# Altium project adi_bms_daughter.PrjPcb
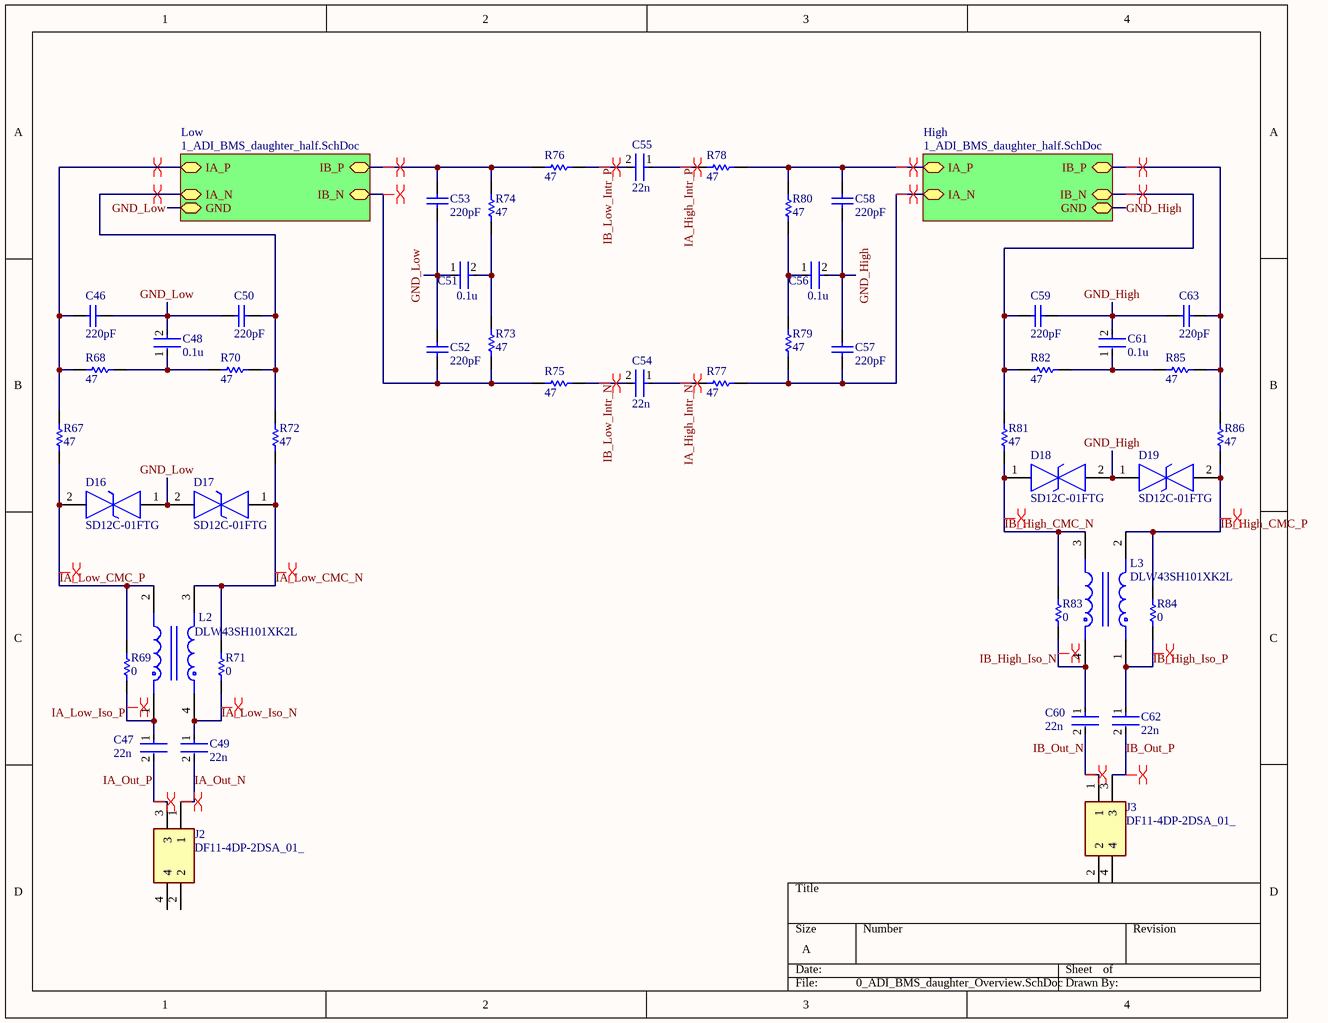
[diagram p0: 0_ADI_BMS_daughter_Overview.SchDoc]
2 sheets, 306 parts. Net scope: hierarchical (ports join the sheet entries above them; power ports are global).
Board file: ADI_BMS_daughter.PcbDoc
Sheets:
  0_ADI_BMS_daughter_Overview.SchDoc
    Low = 1_ADI_BMS_daughter_half.SchDoc
    High = 1_ADI_BMS_daughter_half.SchDoc

## Sheet 0_ADI_BMS_daughter_Overview.SchDoc
size A; SheetNumber: 1; SheetTotal: 2

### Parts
C46  value 220pF  [CAPC0603(1608)100_L]  (hidden comment: CGA3E2C0G2A221J080AA)
C47  22n  [FP-C3225-250-0_4-IPC_B]
C48  0.1u  [CAPC0603(1608)100_L]
C49  22n  [FP-C3225-250-0_4-IPC_B]
C50  value 220pF  [CAPC0603(1608)100_L]  (hidden comment: CGA3E2C0G2A221J080AA)
C51  0.1u  [CAPC0603(1608)100_L]
C52  value 220pF  [CAPC0603(1608)100_L]  (hidden comment: CGA3E2C0G2A221J080AA)
C53  value 220pF  [CAPC0603(1608)100_L]  (hidden comment: CGA3E2C0G2A221J080AA)
C54  22n  [FP-C3225-250-0_4-IPC_B]
C55  22n  [FP-C3225-250-0_4-IPC_B]
C56  0.1u  [CAPC0603(1608)100_L]
C57  value 220pF  [CAPC0603(1608)100_L]  (hidden comment: CGA3E2C0G2A221J080AA)
C58  value 220pF  [CAPC0603(1608)100_L]  (hidden comment: CGA3E2C0G2A221J080AA)
C59  value 220pF  [CAPC0603(1608)100_L]  (hidden comment: CGA3E2C0G2A221J080AA)
C60  22n  [FP-C3225-250-0_4-IPC_B]
C61  0.1u  [CAPC0603(1608)100_L]
C62  22n  [FP-C3225-250-0_4-IPC_B]
C63  value 220pF  [CAPC0603(1608)100_L]  (hidden comment: CGA3E2C0G2A221J080AA)
D16  SD12C-01FTG  [SOD2613X114N]
D17  SD12C-01FTG  [SOD2613X114N]
D18  SD12C-01FTG  [SOD2613X114N]
D19  SD12C-01FTG  [SOD2613X114N]
J2  DF11-4DP-2DSA_01_  [SHDR4W50P200_2X2_600X500X660P]
J3  DF11-4DP-2DSA_01_  [SHDR4W50P200_2X2_600X500X660P]
L2  DLW43SH101XK2L  [FP-DLW43-0_2-t2_6-e0_6-MFG]
L3  DLW43SH101XK2L  [FP-DLW43-0_2-t2_6-e0_6-MFG]
R67  value 47  [RESC0603(1608)_L]  (hidden comment: ESR03EZPJ470)
R68  value 47  [RESC0603(1608)_L]  (hidden comment: ESR03EZPJ470)
R69  value 0  [RESC0603(1608)_L]  (hidden comment: RMCF0603ZT0R00)
R70  value 47  [RESC0603(1608)_L]  (hidden comment: ESR03EZPJ470)
R71  value 0  [RESC0603(1608)_L]  (hidden comment: RMCF0603ZT0R00)
R72  value 47  [RESC0603(1608)_L]  (hidden comment: ESR03EZPJ470)
R73  value 47  [RESC0603(1608)_L]  (hidden comment: ESR03EZPJ470)
R74  value 47  [RESC0603(1608)_L]  (hidden comment: ESR03EZPJ470)
R75  value 47  [RESC0603(1608)_L]  (hidden comment: ESR03EZPJ470)
R76  value 47  [RESC0603(1608)_L]  (hidden comment: ESR03EZPJ470)
R77  value 47  [RESC0603(1608)_L]  (hidden comment: ESR03EZPJ470)
R78  value 47  [RESC0603(1608)_L]  (hidden comment: ESR03EZPJ470)
R79  value 47  [RESC0603(1608)_L]  (hidden comment: ESR03EZPJ470)
R80  value 47  [RESC0603(1608)_L]  (hidden comment: ESR03EZPJ470)
R81  value 47  [RESC0603(1608)_L]  (hidden comment: ESR03EZPJ470)
R82  value 47  [RESC0603(1608)_L]  (hidden comment: ESR03EZPJ470)
R83  value 0  [RESC0603(1608)_L]  (hidden comment: RMCF0603ZT0R00)
R84  value 0  [RESC0603(1608)_L]  (hidden comment: RMCF0603ZT0R00)
R85  value 47  [RESC0603(1608)_L]  (hidden comment: ESR03EZPJ470)
R86  value 47  [RESC0603(1608)_L]  (hidden comment: ESR03EZPJ470)

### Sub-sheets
High = 1_ADI_BMS_daughter_half.SchDoc: IA_P (bidir), IA_N (bidir), IB_P (bidir), IB_N (bidir), GND (bidir)
Low = 1_ADI_BMS_daughter_half.SchDoc: IA_P (bidir), IA_N (bidir), IB_P (bidir), IB_N (bidir), GND (bidir)

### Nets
GND_High: C56.2 C57.2 C58.1 C59.2 C61.2 C63.1 D18.2 D19.1 ; sheet High/GND  [project net GND]
GND_Low: C46.2 C48.2 C50.1 C51.1 C52.2 C53.1 D16.1 D17.2 ; sheet Low/GND  [project net GND]
IA_High_Intr_N: C54.1 R77.2
IA_High_Intr_P: C55.1 R78.2
IA_Low_CMC_N: D17.1 L2.3 R71.2 R72.1
IA_Low_CMC_P: D16.2 L2.2 R67.1 R69.2
IA_Low_Iso_N: C49.1 L2.4 R71.1
IA_Low_Iso_P: C47.1 L2.1 R69.1
IA_N: C50.2 R70.1 R72.2 ; sheet Low/IA_N
IA_N: C57.1 R77.1 R79.1 ; sheet High/IA_N  [a separate net that carries the same name]
IA_Out_N: C49.2 J2.1
IA_Out_P: C47.2 J2.3
IA_P: C46.1 R67.2 R68.2 ; sheet Low/IA_P
IA_P: C58.2 R78.1 R80.1 ; sheet High/IA_P  [a separate net that carries the same name]
IB_High_CMC_N: D18.1 L3.3 R81.1 R83.2
IB_High_CMC_P: D19.2 L3.2 R84.2 R86.1
IB_High_Iso_N: C60.1 L3.4 R83.1
IB_High_Iso_P: C62.1 L3.1 R84.1
IB_Low_Intr_N: C54.2 R75.1
IB_Low_Intr_P: C55.2 R76.1
IB_N: C52.1 R73.1 R75.2 ; sheet Low/IB_N
IB_N: C59.1 R81.2 R82.2 ; sheet High/IB_N  [a separate net that carries the same name]
IB_Out_N: C60.2 J3.1
IB_Out_P: C62.2 J3.3
IB_P: C53.2 R74.2 R76.2 ; sheet Low/IB_P
IB_P: C63.2 R85.1 R86.2 ; sheet High/IB_P  [a separate net that carries the same name]
NetC48_1: C48.1 R68.1 R70.2
NetC51_2: C51.2 R73.2 R74.1
NetC56_1: C56.1 R79.2 R80.2
NetC61_1: C61.1 R82.1 R85.2

Not connected (* = marked no-connect by the designer): J2 2 4; J3 2 4

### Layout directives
differential pair: IA_High_Intr_N, IA_High_Intr_P, IA_Low_CMC_N, IA_Low_CMC_P, IA_Low_Iso_N, IA_Low_Iso_P, IA_N, IA_Out_N, IA_Out_P, IA_P, IB_High_CMC_N, IB_High_CMC_P, IB_High_Iso_N, IB_High_Iso_P, IB_Low_Intr_N, IB_Low_Intr_P, IB_N, IB_Out_N, IB_Out_P, IB_P

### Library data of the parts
C46 C50 C52 C53 C57-C59 C63 = CMP-001-00103-1: Ceramic Capacitor, Multilayer, Ceramic, 100V, 5% +Tol, 5% -Tol, C0G, -/+30ppm/Cel TC, 0.00022uF, Surface Mount, 0603
C47 C49 C54 C55 C60 C62 = CMP-08246-005724-1: Multilayer Ceramic Capacitors 22nF ±5% 1000V C0G SMD 1210; Voltage Rating: 1kV
C48 C51 C56 C61 = CMP-002-00083-1: Ceramic Capacitor, Multilayer, Ceramic, 100V, 10% +Tol, 10% -Tol, X7R, 15% TC, 0.1uF, Surface Mount, 0603 GCJ188R72A104KA01D
D16-D19 = SD12C-01FTG: TVS Diode (Bi-directional); Manufacturer_Name: LITTELFUSE
J2 J3 = DF11-4DP-2DSA_01_: Connector; Manufacturer_Name: Hirose; Manufacturer_Part_Number: DF11-4DP-2DSA(01)
L2 L3 = CMP-06045-000059-1: CMC 100UH 200MA 2LN SMD AEC-Q200; Shielding: Unshielded; Tolerance: 50%; DC Resistance (DCR): 2R; Voltage Rating: 50V; Test Frequency: 1MHz; Number of Lines: 2
R67 R68 R70 R72-R82 R85 R86 = CMP-009-00206-1: Fixed Resistor, Metal Glaze/thick Film, 0.25W, 47ohm, 150V, 5% +/-Tol, 200ppm/Cel, Surface Mount, 0603; Power: 250mW
R69 R71 R83 R84 = CMP-009-00243-1: Fixed Resistor, Metal Glaze/thick Film, 0.1W, 0ohm, Surface Mount, 0603; Power: 100mW

## Sheet 1_ADI_BMS_daughter_half.SchDoc
size 431 x 279 mm; SheetNumber: 2; SheetTotal: 2
Used 2 times, as channels Low, High. Parts and nets are listed once, with the designators drawn on the sheet.
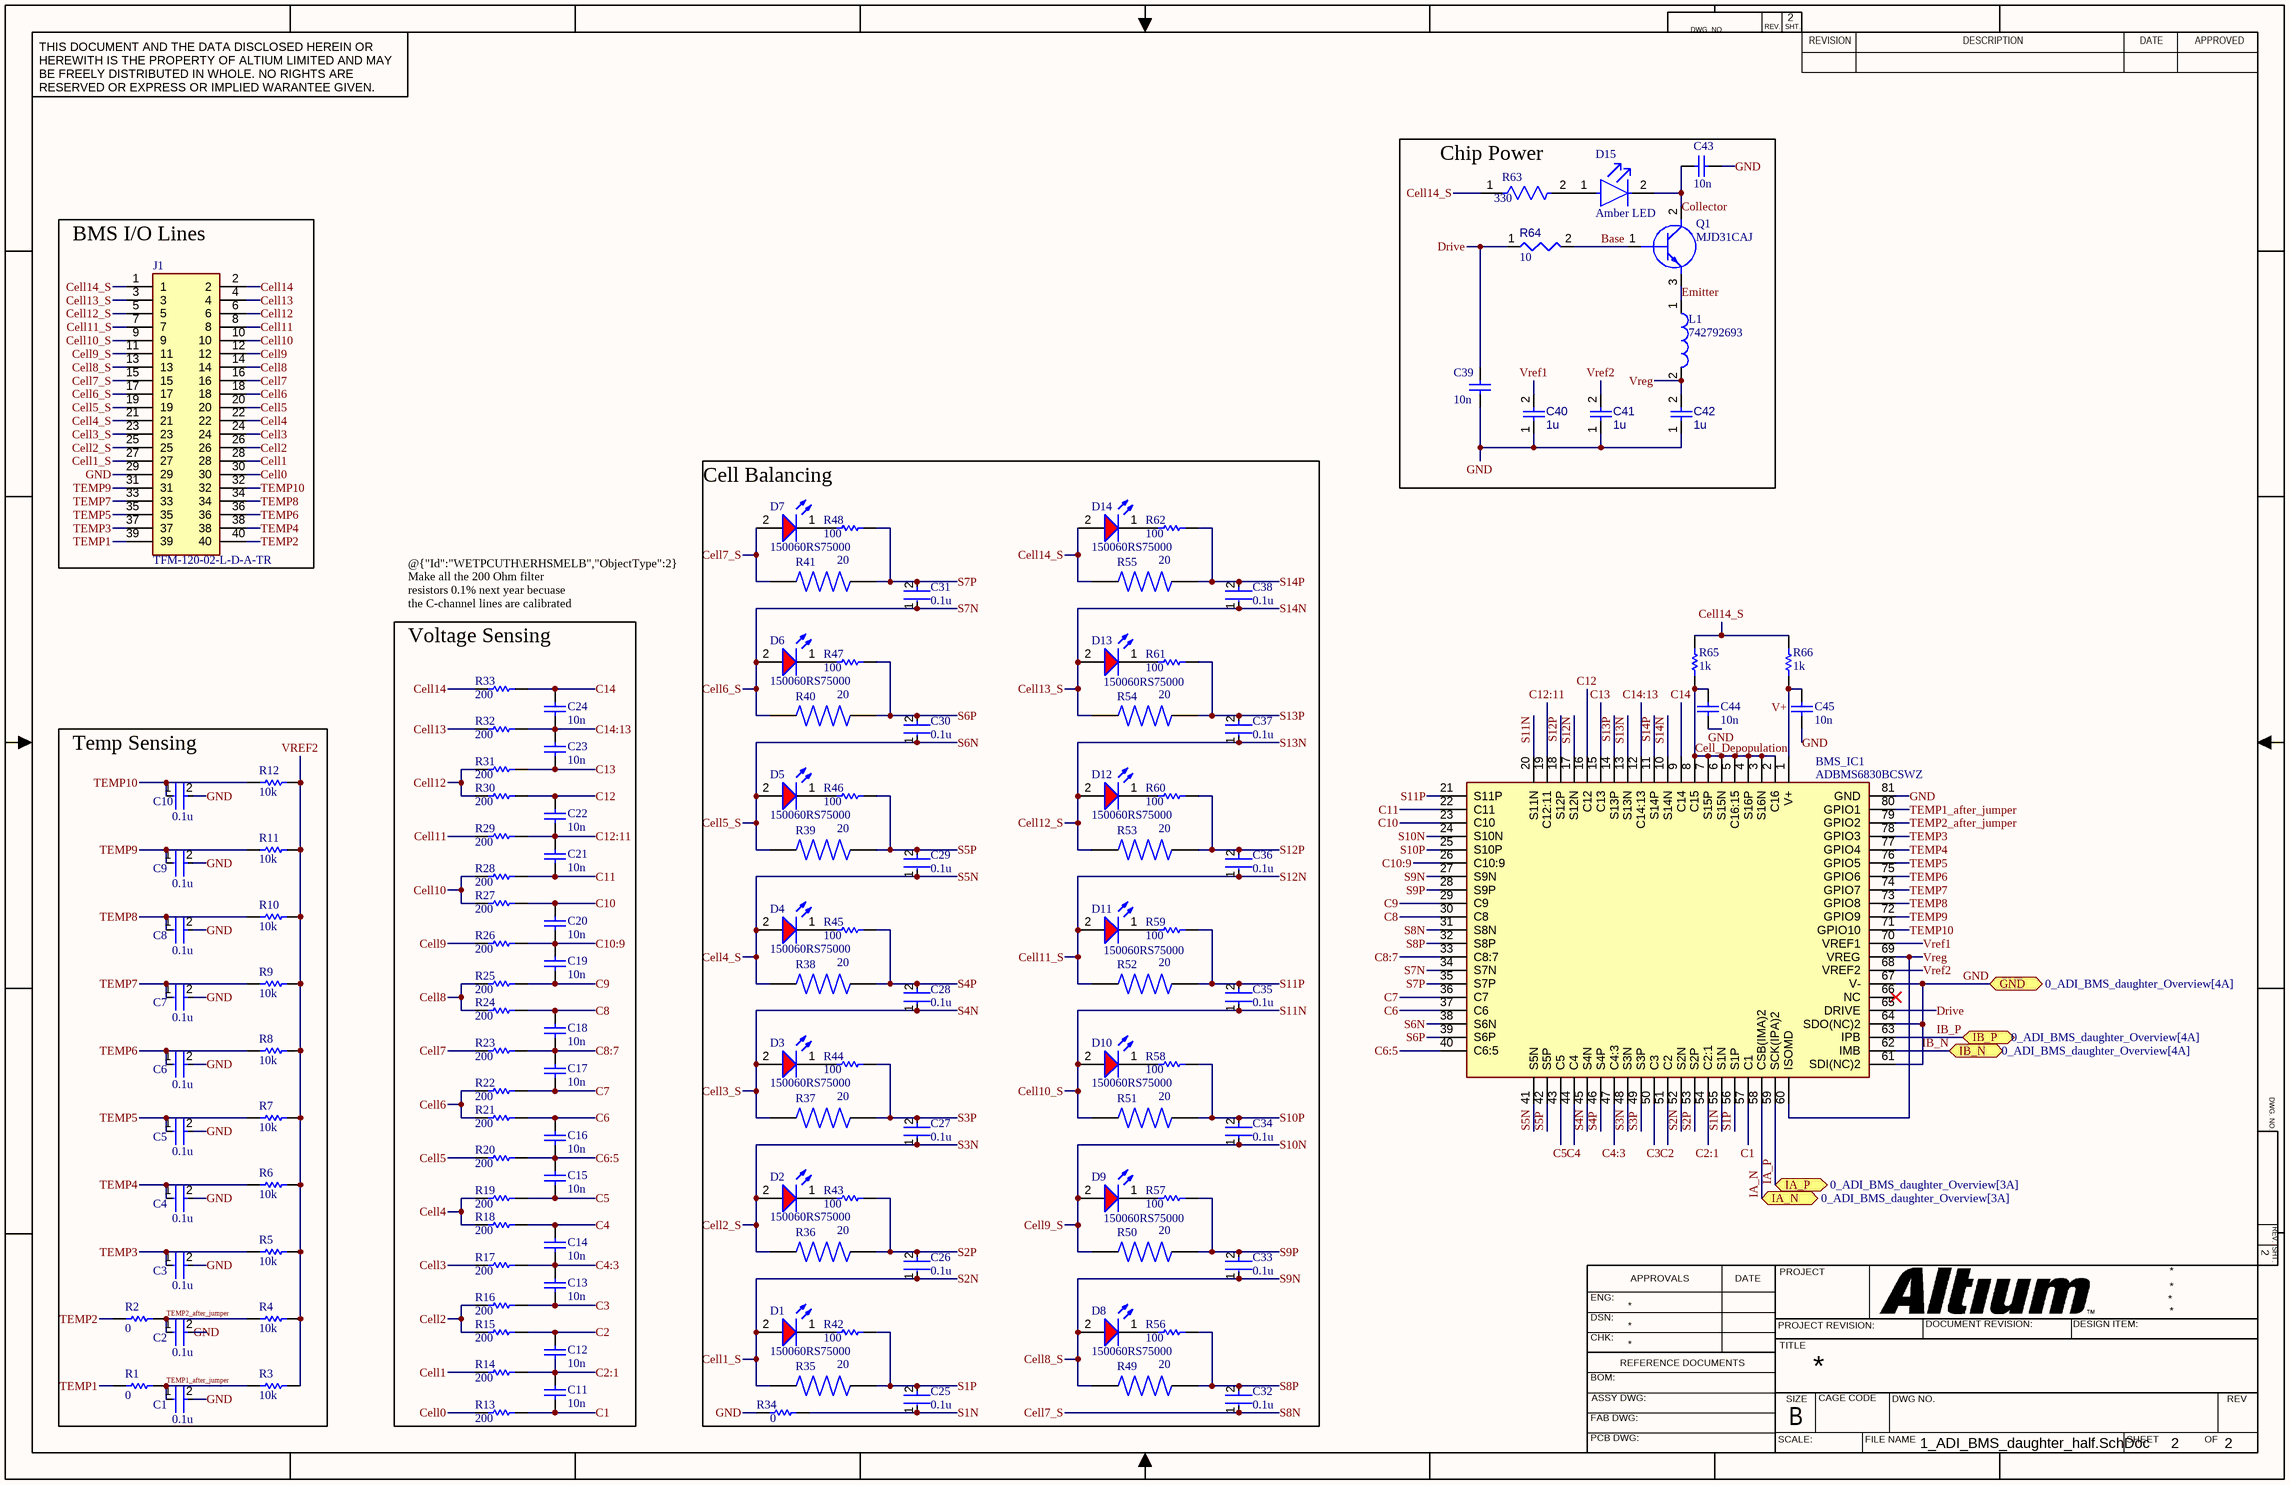
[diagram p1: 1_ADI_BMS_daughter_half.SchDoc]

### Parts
BMS_IC1  ADBMS6830BCSWZ  [QFP50P1400X1400X160-81N]
C1  0.1u  [CAPC0603(1608)100_L]
C2  0.1u  [CAPC0603(1608)100_L]
C3  0.1u  [CAPC0603(1608)100_L]
C4  0.1u  [CAPC0603(1608)100_L]
C5  0.1u  [CAPC0603(1608)100_L]
C6  0.1u  [CAPC0603(1608)100_L]
C7  0.1u  [CAPC0603(1608)100_L]
C8  0.1u  [CAPC0603(1608)100_L]
C9  0.1u  [CAPC0603(1608)100_L]
C10  0.1u  [CAPC0603(1608)100_L]
C11  value 10n  [CAPC0603(1608)100_L]  (hidden comment: C1608X7R2A103K080AA)
C12  value 10n  [CAPC0603(1608)100_L]  (hidden comment: C1608X7R2A103K080AA)
C13  value 10n  [CAPC0603(1608)100_L]  (hidden comment: C1608X7R2A103K080AA)
C14  value 10n  [CAPC0603(1608)100_L]  (hidden comment: C1608X7R2A103K080AA)
C15  value 10n  [CAPC0603(1608)100_L]  (hidden comment: C1608X7R2A103K080AA)
C16  value 10n  [CAPC0603(1608)100_L]  (hidden comment: C1608X7R2A103K080AA)
C17  value 10n  [CAPC0603(1608)100_L]  (hidden comment: C1608X7R2A103K080AA)
C18  value 10n  [CAPC0603(1608)100_L]  (hidden comment: C1608X7R2A103K080AA)
C19  value 10n  [CAPC0603(1608)100_L]  (hidden comment: C1608X7R2A103K080AA)
C20  value 10n  [CAPC0603(1608)100_L]  (hidden comment: C1608X7R2A103K080AA)
C21  value 10n  [CAPC0603(1608)100_L]  (hidden comment: C1608X7R2A103K080AA)
C22  value 10n  [CAPC0603(1608)100_L]  (hidden comment: C1608X7R2A103K080AA)
C23  value 10n  [CAPC0603(1608)100_L]  (hidden comment: C1608X7R2A103K080AA)
C24  value 10n  [CAPC0603(1608)100_L]  (hidden comment: C1608X7R2A103K080AA)
C25  0.1u  [CAPC0603(1608)100_L]
C26  0.1u  [CAPC0603(1608)100_L]
C27  0.1u  [CAPC0603(1608)100_L]
C28  0.1u  [CAPC0603(1608)100_L]
C29  0.1u  [CAPC0603(1608)100_L]
C30  0.1u  [CAPC0603(1608)100_L]
C31  0.1u  [CAPC0603(1608)100_L]
C32  0.1u  [CAPC0603(1608)100_L]
C33  0.1u  [CAPC0603(1608)100_L]
C34  0.1u  [CAPC0603(1608)100_L]
C35  0.1u  [CAPC0603(1608)100_L]
C36  0.1u  [CAPC0603(1608)100_L]
C37  0.1u  [CAPC0603(1608)100_L]
C38  0.1u  [CAPC0603(1608)100_L]
C39  value 10n  [CAPC0603(1608)100_L]  (hidden comment: C1608X7R2A103K080AA)
C40  1u  [CAPC0805(2012)145_L]
C41  1u  [CAPC0805(2012)145_L]
C42  1u  [CAPC0805(2012)145_L]
C43  value 10n  [CAPC0603(1608)100_L]  (hidden comment: C1608X7R2A103K080AA)
C44  value 10n  [CAPC0603(1608)100_L]  (hidden comment: C1608X7R2A103K080AA)
C45  value 10n  [CAPC0603(1608)100_L]  (hidden comment: C1608X7R2A103K080AA)
D1  150060RS75000  [WL-SMCW_0603_150060xx75000]
D2  150060RS75000  [WL-SMCW_0603_150060xx75000]
D3  150060RS75000  [WL-SMCW_0603_150060xx75000]
D4  150060RS75000  [WL-SMCW_0603_150060xx75000]
D5  150060RS75000  [WL-SMCW_0603_150060xx75000]
D6  150060RS75000  [WL-SMCW_0603_150060xx75000]
D7  150060RS75000  [WL-SMCW_0603_150060xx75000]
D8  150060RS75000  [WL-SMCW_0603_150060xx75000]
D9  150060RS75000  [WL-SMCW_0603_150060xx75000]
D10  150060RS75000  [WL-SMCW_0603_150060xx75000]
D11  150060RS75000  [WL-SMCW_0603_150060xx75000]
D12  150060RS75000  [WL-SMCW_0603_150060xx75000]
D13  150060RS75000  [WL-SMCW_0603_150060xx75000]
D14  150060RS75000  [WL-SMCW_0603_150060xx75000]
D15  Amber LED  [FP-CLM3C-AKW-MFG]
J1  TFM-120-02-L-D-A-TR  [TFM12002LDATR]
L1  742792693  [SMD-0603]
Q1  MJD31CAJ  [MJD31CAJ]
R1  value 0  [RESC0603(1608)_L]  (hidden comment: RMCF0603ZT0R00)
R2  value 0  [RESC0603(1608)_L]  (hidden comment: RMCF0603ZT0R00)
R3  value 10k  [RESC0603(1608)_L]  (hidden comment: RT0603BRD0710KL)
R4  value 10k  [RESC0603(1608)_L]  (hidden comment: RT0603BRD0710KL)
R5  value 10k  [RESC0603(1608)_L]  (hidden comment: RT0603BRD0710KL)
R6  value 10k  [RESC0603(1608)_L]  (hidden comment: RT0603BRD0710KL)
R7  value 10k  [RESC0603(1608)_L]  (hidden comment: RT0603BRD0710KL)
R8  value 10k  [RESC0603(1608)_L]  (hidden comment: RT0603BRD0710KL)
R9  value 10k  [RESC0603(1608)_L]  (hidden comment: RT0603BRD0710KL)
R10  value 10k  [RESC0603(1608)_L]  (hidden comment: RT0603BRD0710KL)
R11  value 10k  [RESC0603(1608)_L]  (hidden comment: RT0603BRD0710KL)
R12  value 10k  [RESC0603(1608)_L]  (hidden comment: RT0603BRD0710KL)
R13  value 200  [RESC0603(1608)_L]  (hidden comment: ESR03EZPF2000)
R14  value 200  [RESC0603(1608)_L]  (hidden comment: ESR03EZPF2000)
R15  value 200  [RESC0603(1608)_L]  (hidden comment: ESR03EZPF2000)
R16  value 200  [RESC0603(1608)_L]  (hidden comment: ESR03EZPF2000)
R17  value 200  [RESC0603(1608)_L]  (hidden comment: ESR03EZPF2000)
R18  value 200  [RESC0603(1608)_L]  (hidden comment: ESR03EZPF2000)
R19  value 200  [RESC0603(1608)_L]  (hidden comment: ESR03EZPF2000)
R20  value 200  [RESC0603(1608)_L]  (hidden comment: ESR03EZPF2000)
R21  value 200  [RESC0603(1608)_L]  (hidden comment: ESR03EZPF2000)
R22  value 200  [RESC0603(1608)_L]  (hidden comment: ESR03EZPF2000)
R23  value 200  [RESC0603(1608)_L]  (hidden comment: ESR03EZPF2000)
R24  value 200  [RESC0603(1608)_L]  (hidden comment: ESR03EZPF2000)
R25  value 200  [RESC0603(1608)_L]  (hidden comment: ESR03EZPF2000)
R26  value 200  [RESC0603(1608)_L]  (hidden comment: ESR03EZPF2000)
R27  value 200  [RESC0603(1608)_L]  (hidden comment: ESR03EZPF2000)
R28  value 200  [RESC0603(1608)_L]  (hidden comment: ESR03EZPF2000)
R29  value 200  [RESC0603(1608)_L]  (hidden comment: ESR03EZPF2000)
R30  value 200  [RESC0603(1608)_L]  (hidden comment: ESR03EZPF2000)
R31  value 200  [RESC0603(1608)_L]  (hidden comment: ESR03EZPF2000)
R32  value 200  [RESC0603(1608)_L]  (hidden comment: ESR03EZPF2000)
R33  value 200  [RESC0603(1608)_L]  (hidden comment: ESR03EZPF2000)
R34  value 0  [RESC0603(1608)_L]  (hidden comment: RMCF0603ZT0R00)
R35  value 20  [RESC5025X70N]  (hidden comment: RMCP2010FT20R0)
R36  value 20  [RESC5025X70N]  (hidden comment: RMCP2010FT20R0)
R37  value 20  [RESC5025X70N]  (hidden comment: RMCP2010FT20R0)
R38  value 20  [RESC5025X70N]  (hidden comment: RMCP2010FT20R0)
R39  value 20  [RESC5025X70N]  (hidden comment: RMCP2010FT20R0)
R40  value 20  [RESC5025X70N]  (hidden comment: RMCP2010FT20R0)
R41  value 20  [RESC5025X70N]  (hidden comment: RMCP2010FT20R0)
R42  100  [RESC0603(1608)_L]
R43  100  [RESC0603(1608)_L]
R44  100  [RESC0603(1608)_L]
R45  100  [RESC0603(1608)_L]
R46  100  [RESC0603(1608)_L]
R47  100  [RESC0603(1608)_L]
R48  100  [RESC0603(1608)_L]
R49  value 20  [RESC5025X70N]  (hidden comment: RMCP2010FT20R0)
R50  value 20  [RESC5025X70N]  (hidden comment: RMCP2010FT20R0)
R51  value 20  [RESC5025X70N]  (hidden comment: RMCP2010FT20R0)
R52  value 20  [RESC5025X70N]  (hidden comment: RMCP2010FT20R0)
R53  value 20  [RESC5025X70N]  (hidden comment: RMCP2010FT20R0)
R54  value 20  [RESC5025X70N]  (hidden comment: RMCP2010FT20R0)
R55  value 20  [RESC5025X70N]  (hidden comment: RMCP2010FT20R0)
R56  100  [RESC0603(1608)_L]
R57  100  [RESC0603(1608)_L]
R58  100  [RESC0603(1608)_L]
R59  100  [RESC0603(1608)_L]
R60  100  [RESC0603(1608)_L]
R61  100  [RESC0603(1608)_L]
R62  100  [RESC0603(1608)_L]
R63  Resistance: 330  [FP-ESR18-IPC_A]  (hidden comment: ESR18EZPJ331)
R64  value 10  [RESC0603(1608)_L]  (hidden comment: RMCF0603FT10R0)
R65  value 1k  [RESC0603(1608)_L]  (hidden comment: ESR03EZPJ102)
R66  value 1k  [RESC0603(1608)_L]  (hidden comment: ESR03EZPJ102)

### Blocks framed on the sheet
Chip Power: C39-C43 D15 L1 Q1 R63 R64
BMS I/O Lines: J1
Cell Balancing: C25-C38 D1-D14 R34-R62
Voltage Sensing: C11-C24 R13-R33
Temp Sensing: C1-C10 R1-R12

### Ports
GND (bidir, see 0_ADI_BMS_daughter_Overview[4A]), IA_N (bidir, see 0_ADI_BMS_daughter_Overview[3A]), IA_P (bidir, see 0_ADI_BMS_daughter_Overview[3A]), IB_N (bidir, see 0_ADI_BMS_daughter_Overview[4A]), IB_P (bidir, see 0_ADI_BMS_daughter_Overview[4A])

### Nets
Base: Q1.1(B) R64.2
C1: BMS_IC1.57(C1) C11.1 R13.2
C2: BMS_IC1.51(C2) C12.2 R15.2
C2:1: BMS_IC1.54(C2:1) C11.2 C12.1 R14.2
C3: BMS_IC1.50(C3) C13.1 R16.2
C4: BMS_IC1.44(C4) C14.2 R18.2
C4:3: BMS_IC1.47(C4:3) C13.2 C14.1 R17.2
C5: BMS_IC1.43(C5) C15.1 R19.2
C6: BMS_IC1.37(C6) C16.2 R21.2
C6:5: BMS_IC1.40(C6:5) C15.2 C16.1 R20.2
C7: BMS_IC1.36(C7) C17.1 R22.2
C8: BMS_IC1.30(C8) C18.2 R24.2
C8:7: BMS_IC1.33(C8:7) C17.2 C18.1 R23.2
C9: BMS_IC1.29(C9) C19.1 R25.2
C10: BMS_IC1.23(C10) C20.2 R27.2
C10:9: BMS_IC1.26(C10:9) C19.2 C20.1 R26.2
C11: BMS_IC1.22(C11) C21.1 R28.2
C12: BMS_IC1.16(C12) C22.2 R30.2
C12:11: BMS_IC1.19(C12:11) C21.2 C22.1 R29.2
C13: BMS_IC1.15(C13) C23.1 R31.2
C14: BMS_IC1.9(C14) C24.2 R33.2
C14:13: BMS_IC1.12(C14:13) C23.2 C24.1 R32.2
Cell0: J1.30 R13.1
Cell1: J1.28 R14.1
Cell1_S: BMS_IC1.52(S2N) C26.1 D1.2(A) J1.27 R35.1  [also labelled S2N]
Cell2: J1.26 R15.1 R16.1
Cell2_S: BMS_IC1.48(S3N) C27.1 D2.2(A) J1.25 R36.1  [also labelled S3N]
Cell3: J1.24 R17.1
Cell3_S: BMS_IC1.45(S4N) C28.1 D3.2(A) J1.23 R37.1  [also labelled S4N]
Cell4: J1.22 R18.1 R19.1
Cell4_S: BMS_IC1.41(S5N) C29.1 D4.2(A) J1.21 R38.1  [also labelled S5N]
Cell5: J1.20 R20.1
Cell5_S: BMS_IC1.38(S6N) C30.1 D5.2(A) J1.19 R39.1  [also labelled S6N]
Cell6: J1.18 R21.1 R22.1
Cell6_S: BMS_IC1.34(S7N) C31.1 D6.2(A) J1.17 R40.1  [also labelled S7N]
Cell7: J1.16 R23.1
Cell7_S: BMS_IC1.31(S8N) C32.1 D7.2(A) J1.15 R41.1  [also labelled S8N]
Cell8: J1.14 R24.1 R25.1
Cell8_S: BMS_IC1.27(S9N) C33.1 D8.2(A) J1.13 R49.1  [also labelled S9N]
Cell9: J1.12 R26.1
Cell9_S: BMS_IC1.24(S10N) C34.1 D9.2(A) J1.11 R50.1  [also labelled S10N]
Cell10: J1.10 R27.1 R28.1
Cell10_S: BMS_IC1.20(S11N) C35.1 D10.2(A) J1.9 R51.1  [also labelled S11N]
Cell11: J1.8 R29.1
Cell11_S: BMS_IC1.17(S12N) C36.1 D11.2(A) J1.7 R52.1  [also labelled S12N]
Cell12: J1.6 R30.1 R31.1
Cell12_S: BMS_IC1.13(S13N) C37.1 D12.2(A) J1.5 R53.1  [also labelled S13N]
Cell13: J1.4 R32.1
Cell13_S: BMS_IC1.10(S14N) C38.1 D13.2(A) J1.3 R54.1  [also labelled S14N]
Cell14: J1.2 R33.1
Cell14_S: D14.2(A) J1.1 R55.1 R63.1 R65.1 R66.1
Cell_Depopulation: BMS_IC1.2(C16) BMS_IC1.3(S16N) BMS_IC1.4(S16P) BMS_IC1.5(C16:15) BMS_IC1.6(S15N) BMS_IC1.7(S15P) BMS_IC1.8(C15) C44.2 R65.2
Collector: C43.1 D15.2(C) Q1.2(C)
Drive: BMS_IC1.65(DRIVE) C39.2 R64.1
Emitter: L1.1 Q1.3(E)
GND: BMS_IC1.61(SDI(NC)2) BMS_IC1.64(SDO(NC)2) BMS_IC1.67(V-) BMS_IC1.81(GND) C1.2 C2.2 C3.2 C4.2 C5.2 C6.2 C7.2 C8.2 C9.2 C10.2 C39.1 C40.1 C41.1 C42.1 C43.2 C44.1 C45.2 J1.29 R34.2 ; port GND
IA_N: BMS_IC1.58(CSB(IMA)2) ; port IA_N
IA_P: BMS_IC1.59(SCK(IPA)2) ; port IA_P
IB_N: BMS_IC1.62(IMB) ; port IB_N
IB_P: BMS_IC1.63(IPB) ; port IB_P
S1N: BMS_IC1.55(S1N) C25.1 R34.1
S1P: BMS_IC1.56(S1P) C25.2 R35.2 R42.2
S2P: BMS_IC1.53(S2P) C26.2 R36.2 R43.2
S3P: BMS_IC1.49(S3P) C27.2 R37.2 R44.2
S4P: BMS_IC1.46(S4P) C28.2 R38.2 R45.2
S5P: BMS_IC1.42(S5P) C29.2 R39.2 R46.2
S6P: BMS_IC1.39(S6P) C30.2 R40.2 R47.2
S7P: BMS_IC1.35(S7P) C31.2 R41.2 R48.2
S8P: BMS_IC1.32(S8P) C32.2 R49.2 R56.2
S9P: BMS_IC1.28(S9P) C33.2 R50.2 R57.2
S10P: BMS_IC1.25(S10P) C34.2 R51.2 R58.2
S11P: BMS_IC1.21(S11P) C35.2 R52.2 R59.2
S12P: BMS_IC1.18(S12P) C36.2 R53.2 R60.2
S13P: BMS_IC1.14(S13P) C37.2 R54.2 R61.2
S14P: BMS_IC1.11(S14P) C38.2 R55.2 R62.2
TEMP1: J1.39 R1.2
TEMP1_after_jumper: BMS_IC1.80(GPIO1) C1.1 R1.1 R3.1
TEMP2: J1.40 R2.2
TEMP2_after_jumper: BMS_IC1.79(GPIO2) C2.1 R2.1 R4.1
TEMP3: BMS_IC1.78(GPIO3) C3.1 J1.37 R5.1
TEMP4: BMS_IC1.77(GPIO4) C4.1 J1.38 R6.1
TEMP5: BMS_IC1.76(GPIO5) C5.1 J1.35 R7.1
TEMP6: BMS_IC1.75(GPIO6) C6.1 J1.36 R8.1
TEMP7: BMS_IC1.74(GPIO7) C7.1 J1.33 R9.1
TEMP8: BMS_IC1.73(GPIO8) C8.1 J1.34 R10.1
TEMP9: BMS_IC1.72(GPIO9) C9.1 J1.31 R11.1
TEMP10: BMS_IC1.71(GPIO10) C10.1 J1.32 R12.1
V+: BMS_IC1.1(V+) C45.1 R66.2
Vref1: BMS_IC1.70(VREF1) C40.2
Vref2: BMS_IC1.68(VREF2) C41.2 R3.2 R4.2 R5.2 R6.2 R7.2 R8.2 R9.2 R10.2 R11.2 R12.2
Vreg: BMS_IC1.60(ISOMD) BMS_IC1.69(VREG) C42.2 L1.2
NetD1_1: D1.1(K) R42.1
NetD2_1: D2.1(K) R43.1
NetD3_1: D3.1(K) R44.1
NetD4_1: D4.1(K) R45.1
NetD5_1: D5.1(K) R46.1
NetD6_1: D6.1(K) R47.1
NetD7_1: D7.1(K) R48.1
NetD8_1: D8.1(K) R56.1
NetD9_1: D9.1(K) R57.1
NetD10_1: D10.1(K) R58.1
NetD11_1: D11.1(K) R59.1
NetD12_1: D12.1(K) R60.1
NetD13_1: D13.1(K) R61.1
NetD14_1: D14.1(K) R62.1
NetD15_1: D15.1(A) R63.2

Not connected (* = marked no-connect by the designer): BMS_IC1 66(NC)*

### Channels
Low: designators BMS_IC1=BMS_IC1_Low C1=C1_Low C2=C2_Low C3=C3_Low C4=C4_Low C5=C5_Low C6=C6_Low C7=C7_Low C8=C8_Low C9=C9_Low C10=C10_Low C11=C11_Low C12=C12_Low C13=C13_Low C14=C14_Low C15=C15_Low C16=C16_Low C17=C17_Low C18=C18_Low C19=C19_Low C20=C20_Low C21=C21_Low C22=C22_Low C23=C23_Low C24=C24_Low C25=C25_Low C26=C26_Low C27=C27_Low C28=C28_Low C29=C29_Low C30=C30_Low C31=C31_Low C32=C32_Low C33=C33_Low C34=C34_Low C35=C35_Low C36=C36_Low C37=C37_Low C38=C38_Low C39=C39_Low C40=C40_Low C41=C41_Low C42=C42_Low C43=C43_Low C44=C44_Low C45=C45_Low D1=D1_Low D2=D2_Low D3=D3_Low D4=D4_Low D5=D5_Low D6=D6_Low D7=D7_Low D8=D8_Low D9=D9_Low D10=D10_Low D11=D11_Low D12=D12_Low D13=D13_Low D14=D14_Low D15=D15_Low J1=J1_Low L1=L1_Low Q1=Q1_Low R1=R1_Low R2=R2_Low R3=R3_Low R4=R4_Low R5=R5_Low R6=R6_Low R7=R7_Low R8=R8_Low R9=R9_Low R10=R10_Low R11=R11_Low R12=R12_Low R13=R13_Low R14=R14_Low R15=R15_Low R16=R16_Low R17=R17_Low R18=R18_Low R19=R19_Low R20=R20_Low R21=R21_Low R22=R22_Low R23=R23_Low R24=R24_Low R25=R25_Low R26=R26_Low R27=R27_Low R28=R28_Low R29=R29_Low R30=R30_Low R31=R31_Low R32=R32_Low R33=R33_Low R34=R34_Low R35=R35_Low R36=R36_Low R37=R37_Low R38=R38_Low R39=R39_Low R40=R40_Low R41=R41_Low R42=R42_Low R43=R43_Low R44=R44_Low R45=R45_Low R46=R46_Low R47=R47_Low R48=R48_Low R49=R49_Low R50=R50_Low R51=R51_Low R52=R52_Low R53=R53_Low R54=R54_Low R55=R55_Low R56=R56_Low R57=R57_Low R58=R58_Low R59=R59_Low R60=R60_Low R61=R61_Low R62=R62_Low R63=R63_Low R64=R64#1 R65=R65_Low R66=R66_Low; ports GND=GND IA_N=IA_N IA_P=IA_P IB_N=IB_N IB_P=IB_P
High: designators BMS_IC1=BMS_IC1_High C1=C1_High C2=C2_High C3=C3_High C4=C4_High C5=C5_High C6=C6_High C7=C7_High C8=C8_High C9=C9_High C10=C10_High C11=C11_High C12=C12_High C13=C13_High C14=C14_High C15=C15_High C16=C16_High C17=C17_High C18=C18_High C19=C19_High C20=C20_High C21=C21_High C22=C22_High C23=C23_High C24=C24_High C25=C25_High C26=C26_High C27=C27_High C28=C28_High C29=C29_High C30=C30_High C31=C31_High C32=C32_High C33=C33_High C34=C34_High C35=C35_High C36=C36_High C37=C37_High C38=C38_High C39=C39_High C40=C40_High C41=C41_High C42=C42_High C43=C43_High C44=C44_High C45=C45_High D1=D1_High D2=D2_High D3=D3_High D4=D4_High D5=D5_High D6=D6_High D7=D7_High D8=D8_High D9=D9_High D10=D10_High D11=D11_High D12=D12_High D13=D13_High D14=D14_High D15=D15_High J1=J1_High L1=L1_High Q1=Q1_High R1=R1_High R2=R2_High R3=R3_High R4=R4_High R5=R5_High R6=R6_High R7=R7_High R8=R8_High R9=R9_High R10=R10_High R11=R11_High R12=R12_High R13=R13_High R14=R14_High R15=R15_High R16=R16_High R17=R17_High R18=R18_High R19=R19_High R20=R20_High R21=R21_High R22=R22_High R23=R23_High R24=R24_High R25=R25_High R26=R26_High R27=R27_High R28=R28_High R29=R29_High R30=R30_High R31=R31_High R32=R32_High R33=R33_High R34=R34_High R35=R35_High R36=R36_High R37=R37_High R38=R38_High R39=R39_High R40=R40_High R41=R41_High R42=R42_High R43=R43_High R44=R44_High R45=R45_High R46=R46_High R47=R47_High R48=R48_High R49=R49_High R50=R50_High R51=R51_High R52=R52_High R53=R53_High R54=R54_High R55=R55_High R56=R56_High R57=R57_High R58=R58_High R59=R59_High R60=R60_High R61=R61_High R62=R62_High R63=R63_High R64=R64#2 R65=R65_High R66=R66_High; ports GND=GND IA_N=IA_N IA_P=IA_P IB_N=IB_N IB_P=IB_P

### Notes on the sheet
- @{"Id":"WETPCUTH\ERHSMELB","ObjectType":2} Make all the 200 Ohm filter resistors 0.1% next year becuase the C-channel lines are calibrated for 200 Ohms

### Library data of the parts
BMS_IC1 = ADBMS6830BCSWZ: Integrated Circuit; Manufacturer_Name: Analog Devices
C1-C10 C25-C38 = CMP-002-00083-1: as C48 on sheet 0_ADI_BMS_daughter_Overview
C11-C24 C39 C43-C45 = CMP-009-00202-1: Ceramic Capacitor, Multilayer, Ceramic, 100V, 10% +Tol, 10% -Tol, X7R, 15% TC, 0.01uF, Surface Mount, 0603
C40-C42 = CMP-001-00123-1: Ceramic Capacitor, Multilayer, Ceramic, 100V, 10% +Tol, 10% -Tol, X7S, 22% TC, 1uF, Surface Mount, 0805 / HMK212BC7105KGHTE
D1-D14 = CMP-1426-00001-3: NexarPartId: 29717776; Color: Red; Power Dissipation: 72mW; Max Reverse Voltage (DC): 5V; Peak Wavelength: 630nm; Viewing Angle: 140°; Forward Voltage: 2V; Luminous Intensity: 250mcd; Forward Current: 100mA; Dominant Wavelength: 625nm; Lens Style: Clear, Rectangular; Max Junction Temperature (Tj): 95°C; Test Current: 20mA
D15 = CMP-13977-000023-1: LED AMBER CLEAR 2PLCC SMD; Lens Color: Colorless; Reverse Voltage: 5V; Color: Orange; Test Current: 20mA; Dominant Wavelength: 591nm; Viewing Angle: 120°; Luminous Intensity: 730mcd; Forward Voltage: 2.1V; Number of Elements: 1; Power Dissipation: 130mW
J1 = TFM-120-02-L-D-A-TR: Connector; Manufacturer_Name: SAMTEC
L1 = CMP-0220-00111-1: SMD EMI Suppression Ferrite Bead WE-CBF, Z = 2200 Ohm
Q1 = MJD31CAJ: Transistor BJT NPN; Manufacturer_Name: Nexperia
R1 R2 R34 = CMP-009-00243-1: as R69 on sheet 0_ADI_BMS_daughter_Overview
R3-R12 = CMP-009-00204-1: Fixed Resistor, Thin Film, 0.1W, 10000ohm, 75V, 0.1% +/-Tol, 25ppm/Cel, Surface Mount, 0603; Power: 100mW
R13-R33 = CMP-009-00201-1: Fixed Resistor, Metal Glaze/thick Film, 0.25W, 200ohm, 150V, 1% +/-Tol, 100ppm/Cel, Surface Mount, 0603; Power: 250mW
R35-R41 R49-R55 = RMCP2010FT20R0: 20 Ohms Â±1% 1W Chip Resistor 2010 (5025 Metric) Automotive AEC-Q200 Thick Film; MF: Stackpole Electronics Inc
R42-R48 R56-R62 = CMP-009-00197-1: 100 Ohm Resistor, 150 V, 1/4W, 0603, ESR03EZPF1000
R63 = CMP-08839-029435-1: 330Ω ±5% 0.5W 1206 Anti-Surge Chip Resistor AEC-Q200; Max Power Dissipation: 333mW; Temperature Coefficient: 200ppm/°C
R64 = CMP-009-00205-1: Fixed Resistor, Metal Glaze/thick Film, 0.1W, 10ohm, 75V, 1% +/-Tol, 100ppm/Cel, Surface Mount, 0603; Power: 100mW
R65 R66 = CMP-009-00207-1: Fixed Resistor, Metal Glaze/thick Film, 0.25W, 1000ohm, 150V, 5% +/-Tol, 200ppm/Cel, Surface Mount, 0603; Power: 250mW

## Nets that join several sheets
GND: 0_ADI_BMS_daughter_Overview (8 pins), Low (23 pins)
GND: 0_ADI_BMS_daughter_Overview (8 pins), High (23 pins)
IA_N: 0_ADI_BMS_daughter_Overview (C50.2 R70.1 R72.2), Low (BMS_IC1_Low.58)
IA_N: 0_ADI_BMS_daughter_Overview (C57.1 R77.1 R79.1), High (BMS_IC1_High.58)
IA_P: 0_ADI_BMS_daughter_Overview (C46.1 R67.2 R68.2), Low (BMS_IC1_Low.59)
IA_P: 0_ADI_BMS_daughter_Overview (C58.2 R78.1 R80.1), High (BMS_IC1_High.59)
IB_N: 0_ADI_BMS_daughter_Overview (C52.1 R73.1 R75.2), Low (BMS_IC1_Low.62)
IB_N: 0_ADI_BMS_daughter_Overview (C59.1 R81.2 R82.2), High (BMS_IC1_High.62)
IB_P: 0_ADI_BMS_daughter_Overview (C53.2 R74.2 R76.2), Low (BMS_IC1_Low.63)
IB_P: 0_ADI_BMS_daughter_Overview (C63.2 R85.1 R86.2), High (BMS_IC1_High.63)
